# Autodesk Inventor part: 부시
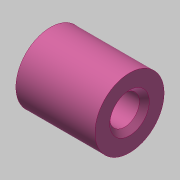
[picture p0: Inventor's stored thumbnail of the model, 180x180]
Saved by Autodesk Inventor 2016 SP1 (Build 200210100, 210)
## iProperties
Created: 2019-02
Part Number: 부시
Material: 스테인리스강
Document SubType Name: Modeling
Designer: mduedu
Density: 1 g/cm^3
Appearance: 분홍색
Author: mduedu
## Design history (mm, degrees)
sketch "스케치1"
  geometry: C1 r 3 at (0, 0); C2 r 7 at (0, 0); 1 further point
  constraints: 2 centre point, 2 coincident
  dimensions: "d0" = 6 diameter of C1; "d1" = 14 diameter of C2
extrude "돌출1" new body sketch "스케치1" stored distance "d2" = 16; taper "d3" = 0 deg
chamfer "모따기1" distance "d4" = 1; stored, may be unused: second distance "d5" = 2, angle "d6" = 45 deg
node "솔리드1"
